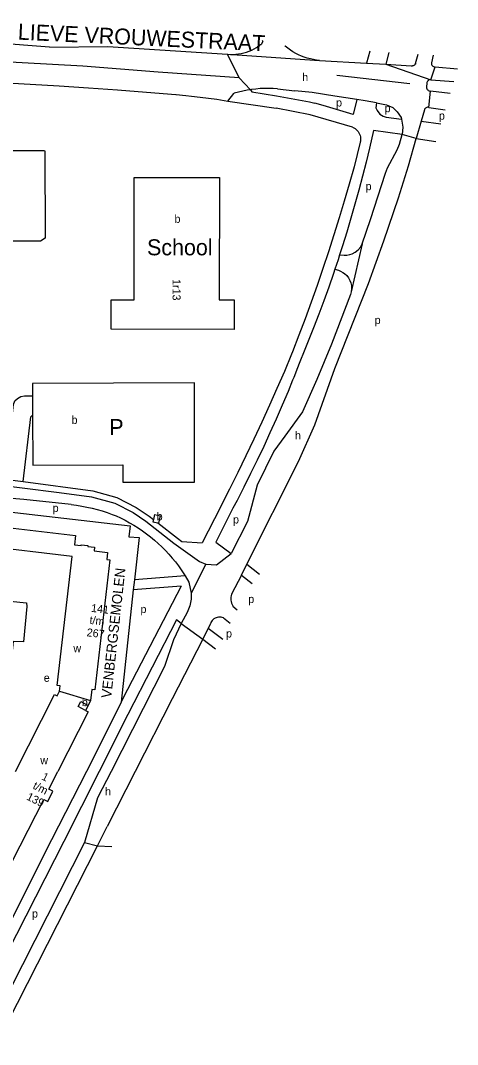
# Model space of a CAD drawing. Extents: x 159902 to 161769, y 383692 to 384875.
# Drawn here: x 161551 to 161769, y 384364 to 384875 of the extents above; entities that cross this region are included whole.
import ezdxf

# ---------------------------------------------------------------- set-up
doc = ezdxf.new("R2010")
doc.units = 0
for name, color, linetype in [('BLT_Basislijn', 7, 'Continuous'), ('BLT_Bebouwing', 7, 'Continuous'), ('BLT_Bebouwing_beschrifting', 7, 'Continuous'), ('BLT_Centroide', 7, 'Continuous'), ('BLT_Huisnummer', 7, 'Continuous'), ('BLT_Huisnummer_reeks', 7, 'Continuous'), ('BLT_Onderverdeling_panden', 7, 'Continuous'), ('BLT_Straatnaam', 7, 'Continuous'), ('BLT_Straatnaam_hoofdweg', 7, 'Continuous'), ('BLT_Tekst_parkeren', 7, 'Continuous'), ('BLT_Vlakafsluiter', 7, 'Continuous')]:
    doc.layers.add(name, color=color, linetype=linetype)

msp = doc.modelspace()

# ---------------------------------------------------------------- linework, layer by layer
at = {"layer": 'BLT_Basislijn'}
for p, q in [((161670.57, 384863.18), (161668.98, 384862.18)), ((161725.08, 384860.07), (161723.52, 384854.1)), ((161734.62, 384859.48), (161733.04, 384853.55)), ((161747.99, 384853.98), (161749.28, 384858.57)), ((161700.04, 384855.45), (161723.52, 384854.1)), ((161723.52, 384854.1), (161733.04, 384853.55)), ((161733.04, 384853.55), (161745.76, 384852.81)), ((161745.76, 384852.81), (161746.07, 384852.79)), ((161746.07, 384852.79), (161746.39, 384852.78)), ((161708.67, 384848.07), (161745.08, 384843.93)), ((161757.79, 384852.28), (161768.89, 384851.2)), ((161753.61, 384843.95), (161753.39, 384842.5)), ((161755.59, 384845.8), (161766.99, 384844.85)), ((161628.32, 384838.35), (161633.2, 384837.85)), ((161654.11, 384835.17), (161657.13, 384838.97)), ((161679.04, 384841.28), (161687.69, 384840.33)), ((161654.11, 384835.17), (161678.26, 384831.62)), ((161718.57, 384835.89), (161716.82, 384828.49)), ((161752.4, 384830.76), (161750.73, 384825.03)), ((161754.6, 384831.92), (161762.76, 384830.78)), ((161750.73, 384825.03), (161748.22, 384816.4)), ((161750.73, 384825.03), (161760.64, 384823.71)), ((161741.28, 384818.41), (161726.9, 384820.46)), ((161720.27, 384814.53), (161717.25, 384802.2)), ((161748.22, 384816.4), (161757.99, 384814.89)), ((161541.46, 384646.31), (161551.89, 384644.93)), ((161534.41, 384631.06), (161605.46, 384622.86)), ((161650.5, 384632.14), (161641.42, 384614.25)), ((161631.21, 384615.05), (161641.42, 384614.25)), ((161648.48, 384603.35), (161655.85, 384608.91)), ((161643.27, 384603.66), (161635.89, 384589.1)), ((161661.03, 384598.1), (161663.76, 384603.58)), ((161663.76, 384603.58), (161670.01, 384598.69)), ((161632.94, 384597.81), (161607.53, 384595.86)), ((161630.61, 384601.35), (161632.94, 384597.81)), ((161661.03, 384598.1), (161656.02, 384588.59)), ((161661.03, 384598.1), (161666.31, 384593.96)), ((161630.84, 384592.64), (161601.97, 384536.78)), ((161607.53, 384595.86), (161606.98, 384590.8)), ((161630.84, 384592.64), (161606.98, 384590.8)), ((161606.98, 384590.8), (161600.91, 384534.66)), ((161656.71, 384582.69), (161658.83, 384580.84)), ((161651.95, 384576.76), (161655.34, 384574.19)), ((161644.4, 384571.68), (161641.64, 384566.23)), ((161645.49, 384573.86), (161644.4, 384571.68)), ((161644.4, 384571.68), (161651.65, 384566.08)), ((161641.64, 384566.23), (161647.98, 384561.33)), ((161622.62, 384552.54), (161595.85, 384500)), ((161601.97, 384536.78), (161600.91, 384534.66)), ((161600.91, 384534.66), (161584.7, 384502.23)), ((161604.23, 384528.44), (161589.91, 384500)), ((161583.57, 384500), (161566.13, 384465.78)), ((161589.91, 384500), (161572.32, 384465.07)), ((161584.7, 384502.23), (161583.57, 384500)), ((161595.85, 384500), (161589.15, 384486.85)), ((161607.99, 384500), (161593.99, 384472.52)), ((161589.15, 384486.85), (161582.61, 384464.51)), ((161589.05, 384462.81), (161593.99, 384472.52)), ((161566.13, 384465.78), (161522.6, 384379.3)), ((161572.32, 384465.07), (161528.61, 384379.3)), ((161582.61, 384464.51), (161535.3, 384371.31)), ((161538.52, 384363.54), (161589.05, 384462.81))]:
    msp.add_line(p, q, dxfattribs=at)
for points in [[(161565.09, 384862.1), (161483.25, 384868.44), (161483.29, 384871.04)], [(161670.86, 384863.44), (161670.66, 384863.24), (161670.57, 384863.18)], [(161671.32, 384865.62), (161671.63, 384864.96), (161670.86, 384863.44)], [(161659.78, 384846.77), (161619.39, 384849.53), (161581.77, 384852.64), (161536.21, 384855.06), (161446.16, 384858.25)], [(161565.09, 384862.1), (161594.25, 384862.45), (161654.1, 384858.54)], [(161654.1, 384858.54), (161655.47, 384858.45), (161656.84, 384858.44), (161658.2, 384858.52), (161659.56, 384858.67), (161660.91, 384858.9), (161662.24, 384859.21), (161663.56, 384859.6), (161664.84, 384860.06), (161666.1, 384860.6), (161667.33, 384861.21), (161668.51, 384861.89), (161668.98, 384862.18)], [(161700.04, 384855.45), (161698.48, 384855.62), (161696.93, 384855.88), (161695.4, 384856.21), (161693.89, 384856.61), (161692.39, 384857.1), (161690.93, 384857.66), (161689.49, 384858.29), (161688.09, 384859), (161686.73, 384859.78), (161685.41, 384860.62), (161684.13, 384861.53), (161682.9, 384862.51), (161682.67, 384862.7)], [(161756.67, 384858.11), (161755.85, 384854.23)], [(161747.99, 384853.98), (161747.86, 384853.65), (161747.66, 384853.35), (161747.4, 384853.1), (161747.09, 384852.92), (161746.75, 384852.81), (161746.39, 384852.78)], [(161755.85, 384854.23), (161755.84, 384853.85), (161755.92, 384853.49), (161756.07, 384853.14), (161756.29, 384852.84), (161756.57, 384852.59), (161756.9, 384852.41), (161757.25, 384852.3), (161757.63, 384852.27), (161757.79, 384852.28)], [(161498.25, 384846.4), (161511.76, 384845.81), (161526.33, 384845.16), (161540.89, 384844.43), (161555.46, 384843.61), (161570.01, 384842.72), (161584.56, 384841.75), (161599.11, 384840.7), (161613.65, 384839.57), (161628.18, 384838.36), (161628.32, 384838.35)], [(161753.39, 384842.5), (161753.36, 384842.11), (161753.41, 384841.71), (161753.54, 384841.33), (161753.74, 384840.98), (161754, 384840.68), (161754.32, 384840.44), (161754.68, 384840.27), (161755.07, 384840.17), (161755.42, 384840.15)], [(161755.59, 384845.8), (161755.21, 384845.8), (161754.83, 384845.72), (161754.49, 384845.56), (161754.18, 384845.33), (161753.93, 384845.04), (161753.75, 384844.71), (161753.64, 384844.34), (161753.61, 384843.95)], [(161633.2, 384837.85), (161635.97, 384837.57), (161640.38, 384837.05)], [(161665.46, 384840.82), (161663.78, 384840.55), (161661.63, 384840.12), (161659.5, 384839.62), (161657.39, 384839.05), (161657.13, 384838.97)], [(161679.04, 384841.28), (161676.85, 384841.41), (161674.66, 384841.47), (161672.48, 384841.44), (161670.29, 384841.34), (161668.11, 384841.15), (161665.94, 384840.89), (161665.46, 384840.82)], [(161665.56, 384840.72), (161666.1, 384839.75), (161678.48, 384837.76), (161694.94, 384834.73), (161697.71, 384834.03)], [(161718.57, 384835.89), (161707.71, 384837.57), (161696.34, 384839.37), (161687.69, 384840.33)], [(161765.21, 384838.95), (161755.42, 384840.15)], [(161640.38, 384837.05), (161648.62, 384836.07), (161654.11, 384835.17)], [(161716.82, 384828.49), (161701.72, 384832.97), (161697.71, 384834.03)], [(161728.45, 384834.19), (161722.82, 384835.23), (161718.57, 384835.89)], [(161728.45, 384834.19), (161728.11, 384831.8), (161728.8, 384830.35), (161730.16, 384828.66), (161731.72, 384827.53), (161733.29, 384827.15), (161740.92, 384826.11)], [(161728.45, 384834.19), (161733.42, 384833.29), (161736.58, 384831.87), (161736.58, 384831.87), (161738.81, 384829.83), (161740.8, 384826.91), (161740.92, 384826.11)], [(161716.5, 384822.07), (161695.36, 384828.34), (161678.26, 384831.62)], [(161754.6, 384831.92), (161754.25, 384832.02), (161753.89, 384832.04), (161753.53, 384831.98), (161753.2, 384831.84), (161752.91, 384831.63), (161752.67, 384831.36), (161752.49, 384831.05), (161752.4, 384830.76)], [(161716.5, 384822.07), (161717.15, 384821.76), (161717.75, 384821.39), (161718.32, 384820.95), (161718.82, 384820.45), (161719.27, 384819.9), (161719.66, 384819.3), (161719.98, 384818.66), (161720.22, 384817.99), (161720.38, 384817.3), (161720.47, 384816.59), (161720.48, 384815.88), (161720.4, 384815.17), (161720.27, 384814.53)], [(161740.92, 384826.11), (161741.52, 384822.07), (161741.28, 384818.41)], [(161726.9, 384820.46), (161724.93, 384811.58), (161723.23, 384804.54), (161721.47, 384797.52), (161719.62, 384790.52), (161717.7, 384783.54), (161715.7, 384776.58), (161713.62, 384769.65), (161711.47, 384762.74), (161710.01, 384758.24)], [(161721.31, 384763.82), (161725.49, 384775.9), (161732.9, 384799.1), (161733.96, 384801.79), (161738.74, 384810.76), (161740, 384813.52), (161741.28, 384818.41)], [(161739.35, 384786.72), (161744.43, 384802.84), (161748.21, 384816.35)], [(161748.21, 384816.35), (161748.22, 384816.4)], [(161717.25, 384802.2), (161714.84, 384793.67), (161712.35, 384785.17), (161709.78, 384776.7), (161707.13, 384768.24), (161704.41, 384759.81), (161701.61, 384751.4), (161698.74, 384743.02), (161695.79, 384734.67), (161692.77, 384726.34), (161689.67, 384718.05), (161686.49, 384709.77), (161686.02, 384708.55)], [(161697.67, 384673.35), (161707.56, 384701.54), (161724.4, 384743.92), (161732.17, 384765.21), (161739.35, 384786.72)], [(161710.01, 384758.24), (161712.3, 384758.03), (161713.63, 384758.1), (161715.15, 384758.39), (161716.29, 384758.79), (161717.8, 384759.56), (161719.32, 384760.78), (161720.54, 384762.31), (161721.31, 384763.82)], [(161710.01, 384758.24), (161709.24, 384755.85), (161707.63, 384751.05)], [(161707.63, 384751.05), (161706.93, 384748.99), (161704.55, 384742.15), (161702.1, 384735.34), (161699.57, 384728.56), (161696.96, 384721.8), (161694.28, 384715.08), (161692.6, 384710.97)], [(161707.63, 384751.05), (161709.41, 384750.59), (161710.44, 384750.18), (161711.67, 384749.5), (161712.53, 384748.88), (161713.61, 384747.89), (161714.44, 384746.84), (161715.17, 384745.52), (161715.6, 384744.3), (161715.9, 384742.9), (161715.99, 384741.34), (161715.84, 384739.8)], [(161715.84, 384739.8), (161715.49, 384738.4), (161706.01, 384713.65), (161698.6, 384695.97), (161691.46, 384679.88), (161682.72, 384667.56), (161677.22, 384660.18), (161673.06, 384651.64), (161668.83, 384643.14), (161664.01, 384624.92), (161655.85, 384608.91)], [(161692.6, 384710.97), (161689.89, 384703.95), (161689.06, 384701.87)], [(161686.02, 384708.55), (161682.41, 384700.01), (161678.72, 384691.51), (161674.97, 384683.05), (161671.14, 384674.61), (161667.24, 384666.21), (161663.26, 384657.84), (161659.22, 384649.51), (161655.1, 384641.21), (161650.91, 384632.94), (161650.5, 384632.14)], [(161689.06, 384701.87), (161687.11, 384696.96), (161686.53, 384695.57)], [(161686.53, 384695.57), (161684.25, 384690), (161681.32, 384683.07), (161678.32, 384676.18), (161675.24, 384669.31), (161672.09, 384662.48), (161668.87, 384655.68), (161665.57, 384648.92), (161662.2, 384642.19), (161658.77, 384635.5), (161656.73, 384631.62)], [(161541.46, 384646.31), (161543.88, 384666.77), (161545.4, 384668.68), (161547.18, 384683.52), (161547.86, 384685.23), (161549.17, 384686.54), (161550.74, 384687.5), (161552.57, 384687.8), (161556.63, 384687.87)], [(161551.89, 384644.93), (161555.88, 384677.28), (161556.67, 384678.17)], [(161663.76, 384603.58), (161689.44, 384654.99), (161697.67, 384673.35)], [(161532.75, 384644.08), (161569.91, 384639.42), (161586.14, 384637.39), (161597.71, 384634.13), (161606.85, 384629.46), (161613.19, 384625.16), (161627.22, 384614.22), (161640.03, 384605.02), (161643.27, 384603.66)], [(161551.89, 384644.93), (161586.74, 384640.34), (161598.81, 384636.94), (161608.39, 384632.05), (161614.96, 384627.58), (161617.04, 384625.96)], [(161576, 384633.44), (161552.3, 384636.04), (161531.91, 384637.69)], [(161576, 384633.44), (161578.62, 384633.1), (161581.22, 384632.69), (161583.81, 384632.19), (161586.39, 384631.62), (161588.94, 384630.97), (161591.48, 384630.24), (161593.99, 384629.44), (161596.47, 384628.56), (161598.38, 384627.82)], [(161598.38, 384627.82), (161600.66, 384626.75), (161602.92, 384625.6), (161605.13, 384624.39), (161607.31, 384623.1), (161609.44, 384621.74), (161611.53, 384620.32), (161613.57, 384618.83), (161615.57, 384617.28), (161617.51, 384615.67), (161619.41, 384613.99), (161621.25, 384612.26), (161623.03, 384610.47), (161624.76, 384608.62), (161626.42, 384606.72), (161628.03, 384604.77), (161629.57, 384602.77), (161630.61, 384601.35)], [(161656.73, 384631.62), (161648.16, 384614.7), (161655.85, 384608.91)], [(161605.46, 384622.86), (161604.8, 384617.31), (161609.84, 384616.92), (161607.53, 384595.86)], [(161619.15, 384624.31), (161629.02, 384616.62), (161631.21, 384615.05)], [(161643.27, 384603.66), (161648.48, 384603.35)], [(161632.94, 384597.81), (161634.77, 384594.69), (161635.89, 384589.1)], [(161635.89, 384589.1), (161635.89, 384586.19), (161635.13, 384582.78), (161633.96, 384579.53), (161630.91, 384574)], [(161656.02, 384588.59), (161655.82, 384587.87), (161655.7, 384587.13), (161655.66, 384586.39), (161655.7, 384585.64), (161655.81, 384584.91), (161656.01, 384584.19), (161656.28, 384583.49), (161656.63, 384582.83), (161656.71, 384582.69)], [(161545.56, 384585.18), (161553.65, 384584.24), (161553.74, 384582.45), (161552.17, 384564.81), (161546.9, 384565.02), (161543.76, 384534.71), (161525.94, 384500)], [(161651.95, 384576.76), (161651.38, 384576.98), (161650.78, 384577.11), (161650.16, 384577.17), (161649.55, 384577.15), (161648.94, 384577.05), (161648.35, 384576.88), (161647.79, 384576.62), (161647.27, 384576.3), (161646.79, 384575.92), (161646.37, 384575.47), (161646, 384574.97), (161645.71, 384574.43), (161645.49, 384573.86)], [(161630.91, 384574), (161628.51, 384575.84), (161604.23, 384528.44)], [(161630.91, 384574), (161627.04, 384565.78), (161622.62, 384552.54)], [(161641.64, 384566.23), (161626.47, 384536.26), (161607.99, 384500)]]:
    msp.add_lwpolyline(points, dxfattribs=at)
at = {"layer": 'BLT_Bebouwing'}
for p, q in [((161556.63, 384687.87), (161556.67, 384678.17)), ((161556.67, 384678.17), (161556.75, 384653.11))]:
    msp.add_line(p, q, dxfattribs=at)
for points in [[(161518.72, 384810.21), (161518.99, 384810.48), (161562.6, 384810.45), (161562.87, 384810.18), (161562.92, 384766.54), (161560.65, 384765.12), (161521.03, 384765.14), (161518.77, 384766.57)], [(161607.41, 384796.99), (161649.95, 384796.97), (161649.92, 384735.84), (161657.3, 384735.81), (161657.32, 384721.02), (161595.86, 384721.06), (161595.86, 384735.85), (161607.38, 384735.85)]]:
    msp.add_lwpolyline(points, close=True, dxfattribs=at)
for points in [[(161637.54, 384644.71), (161637.49, 384694.28), (161556.62, 384693.98), (161556.63, 384687.87)], [(161556.75, 384653.11), (161601.74, 384653.3), (161601.76, 384644.59), (161637.54, 384644.71)], [(161617.59, 384628.4), (161617.04, 384625.96)], [(161617.59, 384628.4), (161620.51, 384627.75)], [(161619.15, 384624.31), (161619.71, 384624.19), (161620.51, 384627.75)], [(161570.14, 384540.13), (161570.44, 384542.8), (161568.95, 384542.97), (161576.46, 384607.55), (161531.49, 384612.79), (161532.71, 384623.29)], [(161532.71, 384623.29), (161578.12, 384617.99), (161577.56, 384613.32), (161580.89, 384612.9), (161580.95, 384613.39), (161584.31, 384613.02), (161584.23, 384612.5), (161587.56, 384612.11), (161587.38, 384610.33), (161594.17, 384609.51), (161593.79, 384605.96), (161595.3, 384605.81), (161587.75, 384540.83), (161586.26, 384541), (161585.63, 384535.56)], [(161617.04, 384625.96), (161616.79, 384624.84), (161619.15, 384624.31)], [(161548.08, 384500), (161567.62, 384538.45), (161568.98, 384537.77), (161570.14, 384540.13)], [(161585.63, 384535.56), (161584.36, 384533.06)], [(161583.11, 384530.58), (161584.43, 384529.91), (161569.28, 384500)], [(161584.36, 384533.06), (161583.11, 384530.58)], [(161542.65, 384447.57), (161562.21, 384486.09), (161564.22, 384485.07), (161566.84, 384490.24), (161564.84, 384491.25), (161569.28, 384500)]]:
    msp.add_lwpolyline(points, dxfattribs=at)
at = {"layer": 'BLT_Onderverdeling_panden'}
msp.add_line((161570.14, 384540.13), (161585.63, 384535.56), dxfattribs=at)
msp.add_lwpolyline([(161583.11, 384530.58), (161579.45, 384532.45), (161580.7, 384534.92), (161584.36, 384533.06)], dxfattribs=at)
at = {"layer": 'BLT_Vlakafsluiter'}
for p, q in [((161659.78, 384846.77), (161654.1, 384858.54)), ((161654.1, 384858.54), (161700.04, 384855.45)), ((161733.04, 384853.55), (161755.59, 384845.8)), ((161755.59, 384845.8), (161757.79, 384852.28)), ((161665.46, 384840.82), (161659.78, 384846.77)), ((161665.56, 384840.72), (161665.46, 384840.82)), ((161754.6, 384831.92), (161755.42, 384840.15)), ((161748.22, 384816.4), (161741.28, 384818.41)), ((161721.31, 384763.82), (161715.84, 384739.8)), ((161630.91, 384574), (161641.64, 384566.23)), ((161582.61, 384464.51), (161589.05, 384462.81)), ((161589.05, 384462.81), (161596.26, 384462.6))]:
    msp.add_line(p, q, dxfattribs=at)

# ---------------------------------------------------------------- texts
at = {"layer": 'BLT_Bebouwing_beschrifting'}
msp.add_text('School', height=8, dxfattribs=at).set_placement((161613.84, 384758.04))
at = {"layer": 'BLT_Centroide'}
for s, p in [('h', (161691.33, 384845.11)), ('p', (161708.25, 384832.41)), ('p', (161732.48, 384829.59)), ('p', (161759.6, 384825.85)), ('p', (161723.02, 384790.6)), ('b', (161627.54, 384774.24)), ('p', (161727.53, 384723.68)), ('b', (161576.14, 384673.78)), ('h', (161687.72, 384666.02)), ('p', (161566.71, 384629.74)), ('b', (161618.66, 384625.58)), ('p', (161656.79, 384623.99)), ('p', (161664.39, 384584.22)), ('p', (161610.56, 384579.21)), ('p', (161653.3, 384567)), ('w', (161577.06, 384559.64)), ('e', (161562.26, 384544.85)), ('b', (161581.25, 384532.68)), ('w', (161560.53, 384503.64)), ('h', (161592.86, 384488.03)), ('p', (161556.39, 384426.99))]:
    msp.add_text(s, height=4, dxfattribs=at).set_placement(p)
at = {"layer": 'BLT_Huisnummer'}
msp.add_text('1r13', height=4, rotation=270.1784, dxfattribs=at).set_placement((161626.56, 384746.16))
at = {"layer": 'BLT_Huisnummer_reeks'}
for s, rotation, p in [('141', 353.352, (161585.73, 384579.85)), ('t/m', 353.3445, (161584.96, 384573.88)), ('267', 353.352, (161583.54, 384567.65)), ('t/m', 333.3445, (161556.45, 384491.63)), ('1', 333.352, (161560.82, 384496.18)), ('139', 333.352, (161553.25, 384486.13))]:
    msp.add_text(s, height=4, rotation=rotation, dxfattribs=at).set_placement(p)
at = {"layer": 'BLT_Straatnaam'}
msp.add_text('VENBERGSEMOLEN', height=5, rotation=83.7189, dxfattribs=at).set_placement((161595.92, 384536.48))
at = {"layer": 'BLT_Straatnaam_hoofdweg'}
msp.add_text('ONZE LIEVE VROUWESTRAAT', height=7.9999, rotation=357.276, dxfattribs=at).set_placement((161516.53, 384867.43))
at = {"layer": 'BLT_Tekst_parkeren'}
msp.add_text('P', height=8, dxfattribs=at).set_placement((161595.01, 384668.18))

doc.saveas('drawing.dxf')
